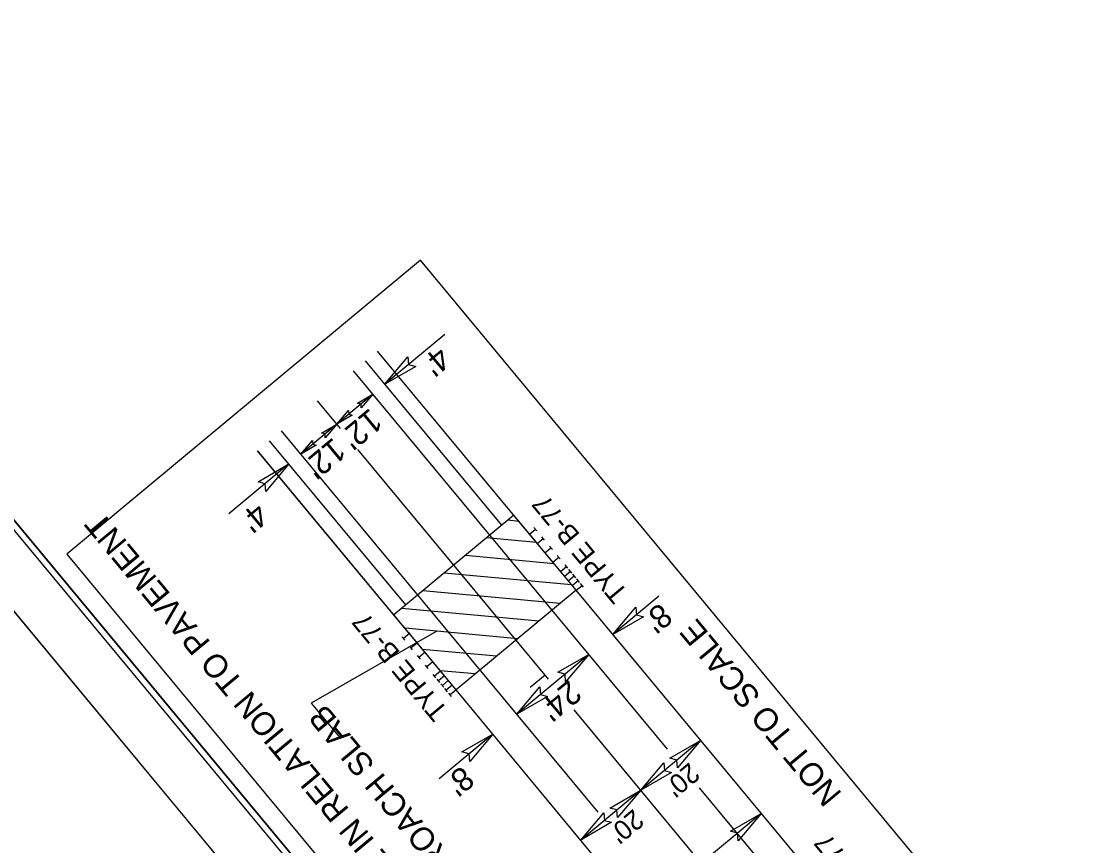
# Model space of a CAD drawing. Extents: x 2597026 to 2598995, y 852197 to 854192.
# Drawn here: x 2597490.1 to 2597902.9, y 852908.6 to 853225.6 of the extents above; entities that cross this region are included whole.
import ezdxf

# ---------------------------------------------------------------- set-up
doc = ezdxf.new("R2010")
doc.units = 0
for name, color, linetype in [('Old_Level_1', 7, 'Continuous'), ('Old_Level_2', 7, 'Continuous'), ('Prop Approach Slab', 7, 'Continuous'), ('Prop Dimension', 7, 'Continuous'), ('Prop Dimension Text', 7, 'Continuous'), ('Prop EOT', 7, 'Continuous'), ('Prop Guardrail', 7, 'Continuous'), ('Prop Horizontal Alignment', 7, 'Continuous'), ('Prop Horizontal Alignment Tick Small', 7, 'Continuous'), ('Prop Paved Shoulder', 7, 'Continuous'), ('Prop Roadway Bridge', 7, 'Continuous'), ('Prop Structure Anchor Unit CELL', 7, 'Continuous'), ('Prop Terminator CELL', 7, 'Continuous'), ('Sheet Clip Boundary CELL', 7, 'Continuous'), ('Sheet Cutting Line CELL', 7, 'Continuous'), ('Sheet Plan CELL', 7, 'Continuous'), ('Sheet Plan Layout CELL', 7, 'Continuous'), ('Sheet Plot Border Inside CELL', 7, 'Continuous'), ('Sheet Plot Border Outside CELL', 7, 'Continuous')]:
    doc.layers.add(name, color=color, linetype=linetype)

msp = doc.modelspace()

# ---------------------------------------------------------------- linework, layer by layer
at = {"layer": 'Old_Level_1'}
for p, q in [((2597507.53, 853020.63), (2597749.73, 852728.97)), ((2597649.97, 852991.01), (2597601.7, 852963.37)), ((2597601.7, 852963.37), (2597612.75, 852950.06))]:
    msp.add_line(p, q, dxfattribs=at)
msp.add_lwpolyline([(2597885.92, 852842.07), (2597643.72, 853133.73), (2597507.53, 853020.63)], dxfattribs=at)
at = {"layer": 'Old_Level_2'}
msp.add_line((2597639.47, 852990.05), (2597581.02, 853060.44), dxfattribs=at)
at = {"layer": 'Prop Approach Slab'}
for p, q in [((2597679.7, 853035.6), (2597633.51, 852997.3)), ((2597703.64, 853006.73), (2597679.7, 853035.6)), ((2597681.63, 853033.26), (2597677.37, 853033.66)), ((2597688.4, 853025.11), (2597669.2, 853026.89)), ((2597695.16, 853016.95), (2597661.03, 853020.11)), ((2597701.93, 853008.79), (2597652.85, 853013.34)), ((2597697.53, 853001.66), (2597644.68, 853006.56)), ((2597657.45, 852968.43), (2597633.51, 852997.3)), ((2597689.36, 852994.89), (2597636.51, 852999.79)), ((2597681.19, 852988.11), (2597637.8, 852992.13)), ((2597673.02, 852981.34), (2597644.56, 852983.97)), ((2597664.84, 852974.56), (2597651.33, 852975.82))]:
    msp.add_line(p, q, dxfattribs=at)
at = {"layer": 'Prop Dimension'}
for p, q in [((2597653.1, 853105.15), (2597630.02, 853085.99)), ((2597625.4, 853082.15), (2597611.56, 853070.66)), ((2597611.56, 853070.66), (2597597.71, 853059.16)), ((2597593.09, 853055.32), (2597570.01, 853036.16)), ((2597735.5, 853004.47), (2597717.75, 852989.73)), ((2597708.52, 852982.07), (2597680.82, 852959.07)), ((2597671.59, 852951.4), (2597650.94, 852934.25)), ((2597751.59, 852948.98), (2597728.51, 852929.82)), ((2597728.51, 852929.82), (2597705.43, 852910.65)), ((2597774.92, 852920.89), (2597728.76, 852882.56))]:
    msp.add_line(p, q, dxfattribs=at)
at = {"layer": 'Prop EOT'}
for p, q in [((2597738.82, 852945.57), (2597617.96, 853091.11)), ((2597712.09, 852921.41), (2597590.27, 853068.12)), ((2597837.27, 852827.03), (2597751.13, 852930.75))]:
    msp.add_line(p, q, dxfattribs=at)
at = {"layer": 'Prop Guardrail'}
for p, q in [((2597685.67, 853028.36), (2597627.2, 853098.78)), ((2597703.64, 853006.73), (2597685.67, 853028.36)), ((2597657.45, 852968.43), (2597639.46, 852990.06))]:
    msp.add_line(p, q, dxfattribs=at)
msp.add_open_spline([(2597581.02, 853060.44), (2597581.08, 853060.37), (2597581.14, 853060.3), (2597581.2, 853060.23), (2597581.5, 853059.86), (2597581.8, 853059.5), (2597582.11, 853059.13), (2597582.41, 853058.77), (2597582.72, 853058.4), (2597583.02, 853058.03), (2597583.32, 853057.67), (2597583.63, 853057.3), (2597583.93, 853056.94), (2597584.23, 853056.57), (2597584.54, 853056.21), (2597584.84, 853055.84), (2597585.14, 853055.48), (2597585.45, 853055.11), (2597585.75, 853054.75), (2597586.05, 853054.38), (2597586.36, 853054.01), (2597586.66, 853053.65), (2597586.96, 853053.28), (2597587.27, 853052.92), (2597587.57, 853052.55), (2597587.87, 853052.19), (2597588.18, 853051.82), (2597588.48, 853051.46), (2597588.78, 853051.09), (2597589.09, 853050.72), (2597589.39, 853050.36), (2597589.7, 853049.99), (2597590, 853049.63), (2597590.3, 853049.26), (2597590.61, 853048.9), (2597590.91, 853048.53), (2597591.21, 853048.17), (2597591.52, 853047.8), (2597591.82, 853047.43), (2597592.12, 853047.07), (2597592.43, 853046.7), (2597592.73, 853046.34), (2597593.03, 853045.97), (2597593.34, 853045.61), (2597593.64, 853045.24), (2597593.94, 853044.88), (2597594.25, 853044.51), (2597594.55, 853044.15), (2597594.85, 853043.78), (2597595.16, 853043.41), (2597595.46, 853043.05), (2597595.77, 853042.68), (2597596.07, 853042.32), (2597596.37, 853041.95), (2597596.68, 853041.59), (2597596.98, 853041.22), (2597597.28, 853040.86), (2597597.59, 853040.49), (2597597.89, 853040.12), (2597598.19, 853039.76), (2597598.5, 853039.39), (2597598.8, 853039.03), (2597599.1, 853038.66), (2597599.41, 853038.3), (2597599.71, 853037.93), (2597600.01, 853037.57), (2597600.32, 853037.2), (2597600.62, 853036.84), (2597600.92, 853036.47), (2597601.23, 853036.1), (2597601.53, 853035.74), (2597601.84, 853035.37), (2597602.14, 853035.01), (2597602.44, 853034.64), (2597602.75, 853034.28), (2597603.05, 853033.91), (2597603.35, 853033.55), (2597603.66, 853033.18), (2597603.96, 853032.81), (2597604.26, 853032.45), (2597604.57, 853032.08), (2597604.87, 853031.72), (2597605.17, 853031.35), (2597605.48, 853030.99), (2597605.78, 853030.62), (2597606.08, 853030.26), (2597606.39, 853029.89), (2597606.69, 853029.52), (2597606.99, 853029.16), (2597607.3, 853028.79), (2597607.6, 853028.43), (2597607.91, 853028.06), (2597608.21, 853027.7), (2597608.51, 853027.33), (2597608.82, 853026.97), (2597609.12, 853026.6), (2597609.42, 853026.24), (2597609.73, 853025.87), (2597610.03, 853025.5), (2597610.33, 853025.14), (2597610.64, 853024.77), (2597610.94, 853024.41), (2597611.24, 853024.04), (2597611.55, 853023.68), (2597611.85, 853023.31), (2597612.15, 853022.95), (2597612.46, 853022.58), (2597612.76, 853022.21), (2597613.06, 853021.85), (2597613.37, 853021.48), (2597613.67, 853021.12), (2597613.97, 853020.75), (2597614.28, 853020.39), (2597614.58, 853020.02), (2597614.89, 853019.66), (2597615.19, 853019.29), (2597615.49, 853018.93), (2597615.8, 853018.56), (2597616.1, 853018.19), (2597616.4, 853017.83), (2597616.71, 853017.46), (2597617.01, 853017.1), (2597617.31, 853016.73), (2597617.62, 853016.37), (2597617.92, 853016), (2597618.22, 853015.64), (2597618.53, 853015.27), (2597618.83, 853014.9), (2597619.13, 853014.54), (2597619.44, 853014.17), (2597619.74, 853013.81), (2597620.04, 853013.44), (2597620.35, 853013.08), (2597620.65, 853012.71), (2597620.96, 853012.35), (2597621.26, 853011.98), (2597621.56, 853011.62), (2597621.87, 853011.25), (2597622.17, 853010.88), (2597622.47, 853010.52), (2597622.78, 853010.15), (2597623.08, 853009.79), (2597623.38, 853009.42), (2597623.69, 853009.06), (2597623.99, 853008.69), (2597624.29, 853008.33), (2597624.6, 853007.96), (2597624.9, 853007.59), (2597625.2, 853007.23), (2597625.51, 853006.86), (2597625.81, 853006.5), (2597626.11, 853006.13), (2597626.42, 853005.77), (2597626.72, 853005.4), (2597627.03, 853005.04), (2597627.33, 853004.67), (2597627.63, 853004.3), (2597627.94, 853003.94), (2597628.24, 853003.57), (2597628.54, 853003.21), (2597628.85, 853002.84), (2597629.15, 853002.48), (2597629.45, 853002.11), (2597629.76, 853001.75), (2597630.06, 853001.38), (2597630.36, 853001.02), (2597630.67, 853000.65), (2597630.97, 853000.28), (2597631.27, 852999.92), (2597631.58, 852999.55), (2597631.88, 852999.19), (2597632.18, 852998.82), (2597632.49, 852998.46), (2597632.79, 852998.09), (2597633.09, 852997.73), (2597633.4, 852997.36), (2597633.7, 852996.99), (2597634.01, 852996.63), (2597634.31, 852996.26), (2597634.61, 852995.9), (2597634.92, 852995.53), (2597635.22, 852995.17), (2597635.52, 852994.8), (2597635.83, 852994.44), (2597636.13, 852994.07), (2597636.43, 852993.71), (2597636.74, 852993.34), (2597637.04, 852992.97), (2597637.34, 852992.61), (2597637.65, 852992.24), (2597637.95, 852991.88), (2597638.25, 852991.51), (2597638.56, 852991.15), (2597638.86, 852990.78), (2597639.16, 852990.42), (2597639.47, 852990.05)], degree=3, dxfattribs=at)
at = {"layer": 'Prop Horizontal Alignment'}
for p, q in [((2597612.99, 853068.93), (2597604.12, 853079.61)), ((2597693.02, 852972.55), (2597619.65, 853060.91)), ((2597750.61, 852903.2), (2597702.87, 852960.69))]:
    msp.add_line(p, q, dxfattribs=at)
at = {"layer": 'Prop Horizontal Alignment Tick Small'}
msp.add_line((2597691.7, 852974.15), (2597685.93, 852969.36), dxfattribs=at)
at = {"layer": 'Prop Paved Shoulder'}
for p, q in [((2597675.06, 853031.75), (2597622.58, 853094.95)), ((2597638.11, 853001.11), (2597585.65, 853064.28))]:
    msp.add_line(p, q, dxfattribs=at)
at = {"layer": 'Prop Roadway Bridge'}
for p, q in [((2597703.64, 853006.73), (2597657.45, 852968.43)), ((2597789.88, 852902.87), (2597703.64, 853006.73)), ((2597743.69, 852864.57), (2597657.45, 852968.43))]:
    msp.add_line(p, q, dxfattribs=at)
at = {"layer": 'Prop Structure Anchor Unit CELL'}
for p, q in [((2597688.53, 853029.62), (2597687.43, 853030.94)), ((2597685.67, 853028.36), (2597687.98, 853030.28)), ((2597703.64, 853006.73), (2597685.67, 853028.36)), ((2597688.66, 853024.76), (2597690.97, 853026.68)), ((2597691.52, 853026.01), (2597690.42, 853027.34)), ((2597691.66, 853021.15), (2597693.97, 853023.07)), ((2597694.52, 853022.41), (2597693.42, 853023.73)), ((2597694.65, 853017.55), (2597696.96, 853019.46)), ((2597697.51, 853018.8), (2597696.41, 853020.12)), ((2597697.65, 853013.94), (2597699.96, 853015.86)), ((2597699.15, 853012.14), (2597701.45, 853014.05)), ((2597700.5, 853015.2), (2597699.41, 853016.52)), ((2597702, 853013.39), (2597700.9, 853014.71)), ((2597700.64, 853010.33), (2597702.95, 853012.25)), ((2597702.14, 853008.53), (2597704.45, 853010.45)), ((2597703.5, 853011.59), (2597702.4, 853012.91)), ((2597705, 853009.79), (2597703.9, 853011.11)), ((2597703.64, 853006.73), (2597705.95, 853008.64)), ((2597706.49, 853007.98), (2597705.4, 853009.31)), ((2597639.48, 852990.07), (2597637.17, 852988.15)), ((2597657.45, 852968.43), (2597639.48, 852990.07)), ((2597637.72, 852987.49), (2597636.62, 852988.81)), ((2597640.72, 852983.89), (2597639.62, 852985.21)), ((2597642.48, 852986.46), (2597640.17, 852984.55)), ((2597643.71, 852980.28), (2597642.61, 852981.6)), ((2597645.47, 852982.86), (2597643.16, 852980.94)), ((2597646.71, 852976.67), (2597645.61, 852977.99)), ((2597648.46, 852979.25), (2597646.16, 852977.33)), ((2597649.7, 852973.07), (2597648.6, 852974.39)), ((2597651.46, 852975.64), (2597649.15, 852973.73)), ((2597651.2, 852971.26), (2597650.1, 852972.59)), ((2597652.96, 852973.84), (2597650.65, 852971.92)), ((2597652.69, 852969.46), (2597651.6, 852970.78)), ((2597654.45, 852972.04), (2597652.15, 852970.12)), ((2597654.19, 852967.66), (2597653.09, 852968.98)), ((2597655.95, 852970.23), (2597653.64, 852968.32)), ((2597657.45, 852968.43), (2597655.14, 852966.52)), ((2597655.69, 852965.85), (2597654.59, 852967.18))]:
    msp.add_line(p, q, dxfattribs=at)
at = {"layer": 'Prop Terminator CELL'}
for points in [[(2597641.89, 853092.82), (2597630.02, 853085.99), (2597638.93, 853096.51), (2597639.14, 853093.56)], [(2597619.47, 853078.74), (2597625.4, 853082.15), (2597620.95, 853076.9), (2597620.85, 853078.37)], [(2597617.49, 853074.07), (2597611.56, 853070.66), (2597616.01, 853075.91), (2597616.11, 853074.44)], [(2597605.62, 853067.24), (2597611.56, 853070.66), (2597607.1, 853065.4), (2597607, 853066.87)], [(2597603.64, 853062.57), (2597597.71, 853059.16), (2597602.16, 853064.42), (2597602.27, 853062.94)], [(2597581.22, 853048.49), (2597593.09, 853055.32), (2597584.18, 853044.8), (2597583.98, 853047.75)], [(2597729.62, 852996.57), (2597717.75, 852989.73), (2597726.66, 853000.25), (2597726.87, 852997.3)], [(2597696.65, 852975.23), (2597708.52, 852982.07), (2597699.61, 852971.55), (2597699.4, 852974.5)], [(2597692.69, 852965.9), (2597680.82, 852959.07), (2597689.73, 852969.59), (2597689.94, 852966.64)], [(2597659.72, 852944.57), (2597671.59, 852951.4), (2597662.68, 852940.88), (2597662.47, 852943.83)], [(2597739.72, 852942.15), (2597751.59, 852948.98), (2597742.68, 852938.46), (2597742.47, 852941.41)], [(2597740.38, 852936.65), (2597728.51, 852929.82), (2597737.42, 852940.34), (2597737.63, 852937.39)], [(2597716.64, 852922.98), (2597728.51, 852929.82), (2597719.6, 852919.3), (2597719.39, 852922.25)], [(2597717.3, 852917.49), (2597705.43, 852910.65), (2597714.34, 852921.17), (2597714.55, 852918.22)], [(2597763.05, 852914.05), (2597774.92, 852920.89), (2597766.01, 852910.37), (2597765.8, 852913.32)]]:
    msp.add_lwpolyline(points, close=True, dxfattribs=at)
at = {"layer": 'Sheet Clip Boundary CELL'}
msp.add_lwpolyline([(2598839.68, 853048.61), (2597945.27, 854125.68), (2597300.19, 853589.99), (2597421.1, 853444.38), (2597258.39, 853309.27), (2598031.89, 852377.81)], close=True, dxfattribs=at)
at = {"layer": 'Sheet Cutting Line CELL'}
msp.add_line((2597077.38, 853492.06), (2598152.9, 852196.9), dxfattribs=at)
at = {"layer": 'Sheet Plan CELL'}
for points in [[(2597105.52, 853493.36), (2598063.83, 852339.35), (2598871.63, 853010.15), (2597913.33, 854164.14)], [(2598871.63, 853010.15), (2598063.87, 852339.34), (2597233.33, 853339.43), (2597348.77, 853435.31), (2597220.99, 853589.21), (2597913.33, 854164.14)]]:
    msp.add_lwpolyline(points, close=True, dxfattribs=at)
at = {"layer": 'Sheet Plan Layout CELL'}
msp.add_lwpolyline([(2598063.87, 852339.34), (2598871.63, 853010.15), (2597913.34, 854164.13), (2597268.25, 853628.44), (2597421.1, 853444.38), (2597258.39, 853309.27)], close=True, dxfattribs=at)
at = {"layer": 'Sheet Plot Border Inside CELL'}
msp.add_lwpolyline([(2598971.62, 852893.67), (2597907.28, 854175.35), (2597095.64, 853501.37), (2598159.98, 852219.68)], close=True, dxfattribs=at)
at = {"layer": 'Sheet Plot Border Outside CELL'}
msp.add_lwpolyline([(2598995.31, 852896.45), (2597919.79, 854191.6), (2597077.38, 853492.06), (2598152.9, 852196.9)], close=True, dxfattribs=at)

# ---------------------------------------------------------------- texts
at = {"layer": 'Old_Level_1'}
for s, p in [('DETAIL SHOWING BRIDGE IN RELATION TO PAVEMENT', (2597726.83, 852789.62)), ('NOT TO SCALE', (2597806.28, 852928.47)), ('BRIDGE APPROACH SLAB', (2597703.44, 852847.12))]:
    msp.add_text(s, height=9, rotation=129.7067, dxfattribs=at).set_placement(p)
at = {"layer": 'Prop Dimension Text'}
for s, height, p in [("4'", 9, (2597650.58, 853101.1)), ("12'", 9, (2597624.29, 853077.14)), ("12'", 9, (2597610.21, 853065.86)), ("4'", 9, (2597580.5, 853040.95)), ("8'", 9, (2597735.88, 853002.28)), ("24'", 9, (2597700.95, 852972.68)), ("20'", 7.5, (2597747.29, 852940.77)), ("8'", 9, (2597659.62, 852939.6)), ("20'", 7.5, (2597725.76, 852922.89))]:
    msp.add_text(s, height=height, rotation=219.7067, dxfattribs=at).set_placement(p)
at = {"layer": 'Prop Structure Anchor Unit CELL'}
for p in [(2597723.97, 853005.81), (2597654.71, 852960.49), (2597832.61, 852875.48)]:
    msp.add_text('TYPE B-77', height=7.5, rotation=129.7067, dxfattribs=at).set_placement(p)

doc.saveas('drawing.dxf')
